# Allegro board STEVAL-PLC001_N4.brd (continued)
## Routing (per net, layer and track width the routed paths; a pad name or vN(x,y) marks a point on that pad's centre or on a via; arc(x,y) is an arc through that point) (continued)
N15516624: length 14.7
  TOP w0.2: v3(35.72,30.91) 36.13,30.91 R71.2 ; TP10.1 46.03,28.37 45.58,27.92 40.71,27.92 39.44,29.2 U13.24 39.44,30.42 38.66,31.2 C54.2
  TOP w0.3: R71.2 37.81,31.78 R72.2 37.84,31.79 C54.2
N15519714: length 19.6
  TOP w0.2: R64.1 45.8,31.78 D27.C 44.9,31.79 R65.1 C50.2 42.96,31.79 42.65,31.48 42.42,31.25 41.39,30.22 U13.21
  TOP w0.3: R64.1 46.48,31.79 51.17,27.1 SW1.2
N15526476: length 2.4
  BOTTOM w0.2: R46.1 77.81,31.55 77.81,31.55 U9.1
N15526659: length 2.4
  BOTTOM w0.2: U7.1 84.06,31.55 84.06,31.55 R32.1
N15526663: length 2.4
  BOTTOM w0.2: U7.2 85.33,31.54 85.31,31.55 R31.1
N15526669: length 2.4
  BOTTOM w0.2: R34.1 86.51,31.55 86.59,31.46 86.59,29.79
N15526673: length 2.4
  BOTTOM w0.2: R36.1 87.81,31.55 87.87,31.5 U7.4
N15644326: length 31.5
  TOP w0.2: v1(37.68,35.36) 37,34.69 R71.1
  POWER PLANE w0.2: v1(37.68,35.36) v1(50.28,47.97)
  LOGIC_PLANE w0.2: v1(54.37,55.8) 53.71,55.14 53.71,50.82 50.86,47.97 v1(50.28,47.97)
  BOTTOM w0.2: R156.2 v1(54.37,55.8)
N15652884: length 20.5
  TOP w0.7: v2(70.65,41.55) 71.69,42.6 71.97,42.6
  TOP w1: 71.97,42.6 72.02,42.65 74.26,42.65 74.31,42.6 L7.2
  BOTTOM w0.4: v2(70.65,41.55) 70.5,41.4 68.51,41.4 68.11,41.8 68.11,43 68.83,43.72 U26.3
  BOTTOM w0.5: C98.1 70.91,42.39 70.91,42.4 ; 70.91,42.4 70.65,42.14 v2(70.65,41.55) ; 70.91,42.4 U26.1
N15653000: length 43
  TOP w0.3: v2(95.45,36.06) 94.88,35.49 75.67,35.49 74.91,36.25 74.91,40.09 74.1,40.9 70.31,40.9 69.93,41.29 69.93,42.77 72.22,45.06 72.22,48.23 71.51,48.94 v2(71.51,50)
  BOTTOM w0.3: 71.67,48.8 71.51,48.95 v2(71.51,50)
  BOTTOM w0.4: v2(95.45,36.06) 96.19,36.8 D48.A
N15853888: length 38.5
  POWER PLANE w0.4: v2(61.71,40.5) 62.66,40.5 68.89,46.73 68.89,46.81 68.93,46.85 68.93,47.02 69.91,47.99 69.91,51.08 69.92,51.09 v2(69.92,51.8)
  BOTTOM w0.4: v2(69.92,51.8) 69.92,56.91 70.85,57.84 R184.2
  BOTTOM w0.6: BT1.1 48.11,40.05 50.56,37.6 59.26,37.6 61.71,40.05 v2(61.71,40.5) BT1.2
N15937224: length 7.2
  TOP w0.2: v1(69.36,81.74) 69.36,82.95 67.67,84.64 v2(66.91,84.64)
  BOTTOM w0.2: U27.104 v1(69.36,81.74)
  BOTTOM w0.3: R163.1 v2(66.91,84.64)
  BOTTOM w0.4: R164.1 R163.1
N15989509: length 58.9
  TOP w0.18: 35.62,32.02 R74.2 35.47,31.87 C53.2 34.73,31.29 34.88,31.14 U13.31
  TOP w0.2: v1(32.02,48.47) 31.98,48.47 28.21,44.7 28.21,35.85 29.63,34.43 35.14,34.43 36.12,33.45 36.12,32.52 35.62,32.02
  POWER PLANE w0.2: v1(32.02,48.47) 34.05,50.51 35.31,50.51 38.18,53.38 57.35,53.38 58.19,54.22 v1(58.19,55.61)
  BOTTOM w0.2: R75.2 57.73,55.67 58.13,55.67 v1(58.19,55.61)
N15989570: length 3.4
  TOP w0.2: R68.2 C55.2 41.21,31.2 40.74,30.73 U13.22
N15989574: length 3.2
  TOP w0.2: R69.2 C57.2 40.31,31.2 40.09,30.98 U13.23
N16126417: length 5.7
  TOP w0.2: v1(45.51,51.4) 45.39,51.52 U15.5
  BOTTOM w0.2: R87.1 42.51,48.8 42.91,49.2 43.31,49.2 v1(45.51,51.4)
N16126447: length 6.5
  TOP w0.18: U15.13 49.38,52.83 49.38,51.9 48.88,51.4 v1(47.91,51.4)
  BOTTOM w0.18: v1(47.91,51.4) 46.92,50.41 46.7,50.41 45.51,49.23 R89.1
N16126488: length 8.3
  TOP w0.18: U15.21 53.39,52.13 53.15,51.89 51.89,51.89 51.57,51.57 51.21,51.57 51.18,51.6 v1(50.31,51.6)
  BOTTOM w0.18: R91.1 49.81,50.96 50.16,50.96 50.31,51.11 v1(50.31,51.6)
N16126496: length 6.2
  TOP w0.18: U15.14 49.89,52.2 49.71,52.02 v1(49.71,51.4)
  BOTTOM w0.18: v1(49.71,51.4) 48.67,51.4 46.51,49.24 R90.2
N16126511: length 5.7
  TOP w0.2: U15.6 45.89,52.18 45.91,52.16 45.91,51.63 v1(46.28,51.26)
  BOTTOM w0.2: v1(46.28,51.26) 46.01,51.26 45.7,50.95 43.76,49.15 43.76,48.91 R88.2
N16423386: length 7.7
  TOP w0.18: v1(50.91,51.16) 52.25,51.16 52.53,51.44 53.36,51.44 53.67,51.75 53.74,51.75 53.89,51.9 U15.22
  BOTTOM w0.18: R92.2 48.75,48.9 48.75,49 v1(50.91,51.16)
N16503177: length 8.7
  TOP w0.3: R81.1 26.71,28.27 D34.C
N16514344: length 78
  TOP w0.8: C86.1 4.32,43 5.61,44.29 ; 5.61,44.11 5.61,44.29 ; 5.61,44.29 Q4.5
  TOP w1: Q4.8 9.47,42.6 8.46,41.6 8.46,32.15 9.46,31.15 14.86,31.15 15.21,30.8 15.21,30.2 14.96,29.95 5.01,29.95 4.71,29.65 4.71,29.2 5.16,28.75 16.16,28.75 16.56,28.35 16.56,27.95 16.16,27.55 6.71,27.55 6.46,27.3 6.46,26.65 6.81,26.3 10.76,26.3 11.11,25.95 11.11,25.4 10.76,25.05 8.31,25.05 8.06,24.8 8.06,24.1 8.31,23.85 11.66,23.85 12.76,22.75 12.76,22.04 12.78,22.02 D39.1
  TOP w1.2: F1.2 12.78,19.66 D39.1
N16514352: length 34
  TOP w0.6: D38.C 7.92,53.97 C90.1 7.97,55.55 R144.1
  TOP w1: Q4.3 Q4.2 Q4.1
  TOP w1.5: C87.1 11.54,47.86 9.74,49.66 Q4.1 9.6,49.8 9.6,52.29 D38.C 9.79,53.99 9.79,60.9 12.63,63.74 L4.1
N16514548: length 12.1
  TOP w0.5: R144.2 7.05,55.55 C90.2
  TOP w0.6: C90.2 7,55.44 4.61,53.05 D38.A
  TOP w0.7: R145.2 3.66,47.35 5.66,49.34 Q4.4 5.66,51.97 D38.A
N16561780: length 5.8
  TOP w0.3: v2(77.28,97.06) 77.28,96.4 76.73,95.85 D11.C
  BOTTOM w0.3: v2(77.28,97.06) 77.28,96.4 76.41,95.53 U6.1
N16578488: length 4.1
  TOP w0.152: v2(71.48,95.8) 71.33,95.8 D10.C
  BOTTOM w0.2: v2(71.48,95.8) 70.32,95.8 69.81,95.3 U3.4
N16596019: length 2.4
  BOTTOM w0.2: U12.2 62.34,22.52 62.36,22.5 R61.1
N16596025: length 2.4
  BOTTOM w0.2: U12.3 61.08,21.95 R60.1
N16605257: length 6.4
  BOTTOM w0.152: R184.1 R185.1
  BOTTOM w0.3: R184.1 70.69,59.08 70.38,59.08 ; 70.38,59.08 70.5,58.95 70.5,58.53 C100.2 ; 70.38,59.08 70.38,59.12 68.86,60.64 U27.6
N16616858: length 1.2
  TOP w0.5: D40.A 7.71,61.21 R142.1
N16634792: length 8.9
  TOP w0.25: D21.A 59.86,23.8 61.67,22 66.63,22 67.11,22.48 R51.1
N16639460: length 2.4
  BOTTOM w0.2: R62.1 63.51,22.5 63.62,22.61 U12.1
N16639519: length 2.4
  BOTTOM w0.2: R59.1 59.81,22.5 59.81,22.5 U12.4
N16642965: length 2.4
  BOTTOM w0.2: 68.39,24.31 68.39,23.3 68.52,23.18 68.52,22.72 68.41,22.62 R57.1
N16642967: length 2.6
  BOTTOM w0.2: R58.1 70.31,23.03 69.67,23.68 U11.1
N16642969: length 2.4
  BOTTOM w0.16: R56.1 67.11,23.06 67.12,23.07 U11.3
N16642971: length 2.6
  BOTTOM w0.2: U11.4 65.86,23.05 65.61,22.81 65.61,22.16 R55.1
N16646826: length 2.7
  BOTTOM w0.2: R53.1 73.46,22.69 74.39,23.63 74.39,24.26
N16646828: length 2.6
  BOTTOM w0.2: R50.1 72.71,22.59 73.12,23 U10.3
N16646830: length 2.9
  BOTTOM w0.2: R54.1 75.41,22.96 75.41,23.37 75.67,23.63 U10.1
N16646832: length 3.2
  BOTTOM w0.2: R49.1 71.95,21.96 72.31,22.32 72.31,23.17 71.86,23.63 U10.4
N16671237: length 2.1
  TOP w0.25: 70.76,11.8 71.88,11.8
  TOP w0.3: 71.88,11.8 72.06,11.8 R29.2 ; 70.76,11.8 70.46,11.8 D15.A
N16671239: length 2.2
  TOP w0.5: R27.2 81.43,12.2 D13.A 80.52,12.21
N16671241: length 1.8
  TOP w0.4: R30.2 65.85,11.66 D16.A
N16671243: length 1.5
  TOP w0.3: D14.A R28.2
N16678102: length 3.7
  TOP w0.2: 64.13,22.5 65.04,22.5 65.3,22.76 65.3,22.93 R52.1
  TOP w0.3: D22.A 63.13,23.07 63.71,22.5 64.13,22.5
N16736638: length 16.7
  TOP w0.3: D41.A v3(93.63,45.35)
  POWER PLANE w0.2: v1(89.01,55.51) 88.56,55.06 88.56,50.03 88.56,50.03 88.56,49.57 88.56,49.57 88.56,46.19 89.26,45.49 93.49,45.49 v3(93.63,45.35)
  BOTTOM w0.2: R143.1 89.3,55.8 v1(89.01,55.51)
N16736836: length 4.2
  TOP w0.2: 91.76,50.59 v1(91.76,50)
  TOP w0.25: U22.2 92.82,51.65 91.76,50.59
  BOTTOM w0.2: U25.5 91.3,49.3 91.76,49.76 v1(91.76,50)
N16736872: length 4.3
  TOP w0.2: 92.38,49.75 92.09,49.46 92.09,49.15 v1(91.74,48.8)
  TOP w0.25: U22.3 92.82,51 92.38,50.56 92.38,49.75
  BOTTOM w0.2: v1(91.74,48.8) 91.71,48.8 U25.6
N16737152: length 7.9
  TOP w0.2: D47.A 94.51,55.6 v2(94.71,55.4)
  BOTTOM w0.25: R149.2 89.7,53.13 90.03,52.8 91.36,52.8 93.96,55.4 v2(94.71,55.4)
N16737156: length 8.5
  LOGIC_PLANE w0.3: v1(92.41,57.51) 92.41,58.06 91.73,58.74 v1(90.62,58.74)
  BOTTOM w0.2: Q5.1 93.06,58.23 93.51,58.68 93.51,59.4 94.51,60.4 94.51,61.2 94.52,61.21 R151.1
  BOTTOM w0.3: Q5.1 92.69,57.88 92.41,57.6 v1(92.41,57.51) ; v1(90.62,58.74) R148.2
N16737176: length 3.5
  TOP w0.4: D47.C v1(96.11,57.35)
  BOTTOM w0.4: v1(96.11,57.35) 96.11,57.95 96.11,58.6 95.51,59.2 Q5.3
N16752352: length 10.5
  TOP w0.4: R37.2 90.03,13.8 J8.1
N16753248: length 12.3
  TOP w0.4: 91.21,14.6 R38.2
  TOP w0.5: 91.21,14.6 92.25,14.6 J9.1
N16769682: length 42.9
  TOP w0.8: 94.55,61.15 D46.4 ; D45.4 93.6,40.6
  TOP w0.99: L7.1 89.4,40.8
  TOP w1: 91.43,40.6 D45.4 ; 91.43,40.6 89.6,40.6 89.4,40.8 ; 91.43,40.6 84.41,47.62 84.41,59.18 86.38,61.15 D46.4
N16781010: length 6.2
  TOP w0.2: v1(50.01,68.6) 50.57,69.16 53.36,69.16 R165.1
  BOTTOM w0.2: v1(50.01,68.6) 50.41,69 U27.48
N16815309: length 4.1
  BOTTOM w0.2: R104.1 79.22,85 79.23,85.01 J18.1
N16815311: length 3.2
  BOTTOM w0.3: J18.2 88.49,85.01 88.5,85 89.25,85 R115.2
N16815356: length 4.1
  BOTTOM w0.2: R105.1 79.21,82.45 79.23,82.47 J18.3
N16815358: length 9.2
  BOTTOM w0.3: R106.2 92.45,81.9 92.15,81.6 89.41,81.6 88.54,82.47 J18.4
N16815404: length 4.1
  BOTTOM w0.2: J18.5 79.23,79.93 79.2,79.9 R108.1
N16815406: length 3.5
  TOP w0.3: R109.2 83.85,79.2 v1(84.71,79.2)
  BOTTOM w0.3: J18.6 85.44,79.93 v1(84.71,79.2)
N16815431: length 28.8
  BOTTOM w0.2: J17.14 24.43,69.72 23.51,68.8 23.51,51.4 24.11,50.8 26.71,50.8 28.11,49.4 R186.2
N16815500: length 20.1
  BOTTOM w0.25: R95.1 R96.1 29.19,71.09 24,71.09 22.71,69.8 22.71,61.17 21.09,59.56 J17.21
N16815530: length 4.2
  BOTTOM w0.25: J18.11 79.23,72.31 78.94,72.6 R113.1
N16815532: length 3.1
  BOTTOM w0.3: R118.2 88.5,72.3 88.49,72.31 J18.12
N16815574: length 4.5
  BOTTOM w0.2: R121.1 77.54,69 78.31,69.77 J18.13
N16815576: length 3.2
  BOTTOM w0.3: J18.14 88.49,69.77 88.52,69.8 R122.2
N16815612: length 3.2
  BOTTOM w0.3: R123.2 88.56,67.25 88.54,67.23 J18.16
N16815702: length 7
  BOTTOM w0.2: J18.19 80.17,62.15 79.51,61.49 79.51,60.65 76.97,58.11 R189.1
N16815735: length 3.1
  BOTTOM w0.25: 87.56,59.61 88.14,60.2 R131.2
  BOTTOM w0.3: 87.56,59.61 J18.22
N16815777: length 3.1
  BOTTOM w0.3: J18.24 88.49,57.07 88.51,57.05 R134.2
N16815800: length 6.8
  BOTTOM w0.3: R187.2 28.3,50.2 26.55,51.94 J17.28
N16815809: length 3.1
  BOTTOM w0.3: J18.26 88.49,54.53 88.51,54.55 R135.2
N16815841: length 3.2
  BOTTOM w0.3: J18.28 88.82,51.99 89.06,51.75 R136.2
N16815880: length 4.3
  BOTTOM w0.3: R138.2 87.16,51 86.59,50.43 J18.30
N16815921: length 34.7
  TOP w0.25: v2(83.71,70) 83.71,69.37 83.3,68.96 v2(83.3,54.26)
  BOTTOM w0.25: v2(83.3,54.26) 83.3,48.11 82.09,46.91 J18.31 ; v2(83.71,70) 83.71,72.8 82.91,73.6 77.52,73.6 R190.1
N16815961: length 25.5
  BOTTOM w0.3: R98.1 39.17,48.6 39.51,48.6 39.91,48.2 39.91,47.11 39.95,47.07 39.95,46.66 39.91,46.62 39.91,46.4 39.31,45.8 37.51,45.8 32.92,41.21 30.26,41.21 30.25,41.2 28.11,41.2 27.51,40.6 23.26,40.6 22.08,41.78 J17.35
N16815963: length 3.9
  BOTTOM w0.2: R188.2 28.63,41.78 J17.36
N16815968: length 3.1
  BOTTOM w0.2: R139.2 88.52,44.4 88.49,44.37 J18.34
N16815983: length 27.8
  BOTTOM w0.3: J17.37 19.16,39.24 17.91,40.49 17.91,42.4 18.51,43 33.31,43 34.51,44.2 34.52,44.2 34.81,44.49 34.81,44.5 36.71,46.4 36.71,47.96 37.41,48.66 R99.1
N16816031: length 2.4
  BOTTOM w0.2: U19.59 45.15,74.7 R101.1
N16816085: length 3.1
  BOTTOM w0.2: U19.56 45.05,76.2 45.31,75.94 45.31,75.09 45.86,74.55 R103.1
N16816140: length 2
  BOTTOM w0.25: U19.54 45.41,77.2 45.56,77.05 R116.1
N16816178: length 2
  BOTTOM w0.25: U19.53 45.41,77.7 45.56,77.85 R111.1
N16816234: length 2
  BOTTOM w0.25: U19.51 45.46,78.7 45.56,78.6 R117.1
N16816260: length 2
  BOTTOM w0.25: U19.50 45.41,79.2 45.56,79.35 R120.1
N16816337: length 2.3
  BOTTOM w0.2: U19.48 44.82,80.2 45.46,80.84 45.94,80.84 R125.1
N16816363: length 2.4
  BOTTOM w0.2: U19.47 44.81,80.7 45.91,81.8 R128.1
N16816449: length 2.4
  BOTTOM w0.25: R133.1 45.95,82.65 45.62,82.32 45.62,82.2 45.34,81.92 45.23,81.92 45,81.7 U19.45
N16816548: length 3.9
  TOP w0.3: R137.2 12.61,85.2 D37.A
N16816568: length 3.9
  TOP w0.3: D36.A 12.61,81.2 R94.2
N16816730: length 21.7
  TOP w0.3: v2(28.06,86.8) 25.84,84.58 16.49,84.58 14.81,86.26 11.84,86.26 11.3,86.8 D37.C
  BOTTOM w0.3: Q3.3 v2(28.06,86.8)
N16816751: length 26.6
  TOP w0.5: D36.C 9.51,82.8 10.11,83.4 v2(10.23,83.4)
  BOTTOM w0.3: Q2.3 33.62,86.2 33.03,86.8 30.49,86.8 29.87,86.18 28.8,86.18 28.42,86.18 13.01,86.18 v2(10.23,83.4)
N16816773: length 24.1
  BOTTOM w0.3: R102.1 36.62,88.61 36.33,88.32 Q2.1 36.7,87.17 37.91,88.38 37.91,89.2 38.91,90.2 49.91,90.2 53.09,87.02 54.05,87.02 R97.2
N16816793: length 3.7
  BOTTOM w0.2: Q3.1 33.47,87.77 R140.2 R141.1
N16817624: length 5.1
  BOTTOM w0.2: R130.1 76.97,64.75 R129.1
  BOTTOM w0.25: J18.17 79.2,64.69 79.12,64.6 77.73,64.6 77.64,64.7 R129.1
N16822475: length 3.9
  TOP w0.2: C4.1 32.68,92.08 31.13,92.08 30.73,92.48 U1.48
  TOP w0.3: R1.1 C4.1
N16822477: length 3.3
  TOP w0.2: U1.47 29.8,91.81 30,91.6 30.7,91.6 31.2,91.1 C3.1 R2.1
N16822479: length 2.3
  TOP w0.2: U1.46 29.3,91.32 C2.1 R3.1
N16822481: length 1.6
  TOP w0.2: U1.44 28.3,91.82 28.26,91.79 28.26,91.52 27.85,91.11 R4.1
N16822499: length 23
  TOP w0.2: U1.41 26.8,91.83 25.22,90.25 23.21,90.25 16.31,97.15 D1.A
N16822523: length 25.2
  TOP w0.2: U1.40 26.3,91.91 24.99,90.61 23.45,90.61 16.81,97.25 16.81,103.9 18.4,105.48 18.9,105.48 18.91,105.5 D2.A
N16822549: length 1.5
  TOP w0.2: U1.42 27.19,92.37 27.19,91.53 26.96,91.3 R5.1
N16822551: length 31
  TOP w0.2: U1.39 25.8,91.9 24.89,91 23.61,91 17.38,97.23 17.38,103.53 18.45,104.6 21.66,104.6 22,104.94 v2(22.43,105.37)
  TOP w0.4: D3.A 26.96,105.45 27.51,106 v2(27.6,106)
  BOTTOM w0.2: v2(27.6,106) 26.54,104.94 22.86,104.94 v2(22.43,105.37)
N16822575: length 30.8
  TOP w0.2: v2(18.03,101.2) 18.03,97.08 23.71,91.4 24.68,91.4 25.3,92.02 U1.38
  TOP w0.4: v2(30.64,105) 30.71,105 31.16,105.45 D4.A
  BOTTOM w0.2: v2(18.03,101.2) 18.03,102.86 18.06,102.89 18.06,102.95 19.42,104.31 29.96,104.31 v2(30.64,105)
N16822613: length 33.8
  TOP w0.2: U1.37 24.8,92.24 24.47,91.92 23.84,91.92 18.72,97.04 v2(18.72,100.6)
  TOP w0.4: v2(36.11,104.4) 36.86,105.15 D5.A
  BOTTOM w0.2: v2(18.72,100.6) 18.72,103.06 19.41,103.75 19.66,103.75 19.86,103.95 35.66,103.95 v2(36.11,104.4)
N16822638: length 36.3
  TOP w0.2: v2(19.36,100) 19.36,96.9 23.15,93.11 U1.36
  TOP w0.4: v2(38.91,105.8) 39.62,105.8 40.02,105.4 D6.A
  BOTTOM w0.2: v2(38.91,105.8) 36.71,103.6 20,103.6 19.36,102.96 v2(19.36,100)
N16822654: length 37.1
  TOP w0.2: v2(20.71,100) 20.26,99.55 20.26,96.55 23.2,93.61 U1.35
  TOP w0.4: v2(45.51,105) 45.91,105.4 D7.A
  BOTTOM w0.2: v2(45.51,105) 38.71,105 34.48,100.77 21.48,100.77 v2(20.71,100)
N16822678: length 42.2
  TOP w0.2: U1.34 23.3,94.11 21.4,96.01 v2(21.4,99)
  TOP w0.4: D8.A 52.71,105.4 v2(53.31,104.8)
  BOTTOM w0.2: v2(53.31,104.8) 51.66,104.8 47.27,100.41 22.8,100.41 21.4,99.01 v2(21.4,99)
N16822815: length 2.5
  TOP w0.2: R6.1 32.46,94.05 31.52,93.11 U1.1
N16822888: length 6.1
  TOP w0.4: R8.2 34.16,94.85 36.01,96.7 36.01,97.56 J2.2
N16822890: length 2.6
  TOP w0.18: U1.2 31.37,93.61 32.47,94.71 32.86,94.71 R8.1
N16822932: length 2.5
  TOP w0.18: U1.4 31.57,94.61 32.61,95.65 R10.1
N16823099: length 11.1
  TOP w0.4: J4.2 40.37,100.5 37.21,100.5 35.23,98.52 35.23,96.97 R10.2
N16823193: length 5.1
  TOP w0.2: 30.3,99.25 31.81,99.25 31.82,99.26 C11.1
  TOP w0.3: C11.1 33.5,99.26 34.68,100.44 R13.2
N16823195: length 5.3
  TOP w0.2: R15.2 R16.1 32.76,100.7 32.06,100 30,100 29.8,99.8 29.8,99.25
N16823486: length 4.4
  BOTTOM w0.2: 43.84,87.46 44.36,86.95 R20.2 ; 43.84,87.46 U2.4 ; 43.84,87.46 43.36,86.98 R18.2
N16823562: length 61.2
  POWER PLANE w0.2: v1(37.85,55.62) 38.91,56.68 55.51,56.68 55.53,56.7 57.41,56.7 58.36,57.65 58.61,57.65 v1(58.96,58.01)
  BOTTOM w0.18: 40.04,87.52 40.31,87.25 40.31,68.62 40.35,68.58 40.35,68.22 40.31,68.18 40.31,58.1 38.26,56.05 ; 37.81,55.6 37.85,55.64
  BOTTOM w0.2: v1(58.96,58.01) 59.25,58.3 59.25,58.48 R21.2 ; v1(37.85,55.62) 37.85,55.64 38.26,56.05
  BOTTOM w0.3: 40.04,87.52 U2.7
  BOTTOM w0.4: 40.04,87.52 39.71,87.2 39.71,86.55 38.71,85.55 TP2.1
N16919862: length 13.3
  BOTTOM w0.2: R162.1 73.96,83.28 71.68,81 69,81 68.8,81.2 68.8,82.82 U27.103 68.86,83.74 R161.1
N16919990: length 8.4
  BOTTOM w0.2: R153.1 53.4,56.6 52.71,56.6 52.51,56.8 52.51,58.86 52.71,59.06 R152.1 54.26,59.31 54.26,59.75 54.35,59.84 54.35,60.68 54.36,60.69 U27.35
N16946294: length 3.6
  BOTTOM w0.2: R159.1 R160.1 68.36,85.04 U27.102
N164994551: length 1.7
  TOP w0.2: U5.14 91.46,99.55 91.11,99.9 R26.2
N164999121: length 9.8
  TOP w0.3: R76.1 23.01,25.64 D29.C
N165089721: length 5.6
  TOP w0.4: v1(43.23,44.6) 42.8,45.02 40.09,45.02 39.73,44.67 Q1.1
  BOTTOM w0.3: R84.2 43.75,44.6 v1(43.23,44.6)
N170697731: length 6.5
  BOTTOM w0.2: R191.2 92.87,67.55 92.87,68.8
  BOTTOM w0.3: 92.87,68.8 92.87,69.51 93.29,69.93 J23.7
N1681503127: length 2.8
  BOTTOM w0.25: R100.2 31.01,74.3 31.41,74.7 U19.28
N1681503130: length 2.7
  BOTTOM w0.25: R114.2 31.51,76 31.71,76.2 U19.31
N1681503132: length 2.8
  BOTTOM w0.25: R107.2 31.31,76.8 31.71,77.2 U19.33
N1681503133: length 2.7
  BOTTOM w0.25: R110.2 32.07,77.6 32.17,77.7 U19.34
N1681503135: length 2.9
  BOTTOM w0.25: U19.36 31.63,78.7 31.32,79.01 31.32,79.01 31.04,79.3 R112.2
N1681503136: length 3
  BOTTOM w0.25: U19.37 31.86,79.2 31.01,80.05 R119.2
N1681503138: length 2.9
  BOTTOM w0.25: U19.39 31.71,80.2 31.01,80.9 R124.2
N1681503139: length 3.1
  BOTTOM w0.25: U19.40 32.17,80.7 31.12,81.75 R127.2
N1681503141: length 3
  BOTTOM w0.25: U19.42 32.17,81.7 31.27,82.6 R132.2

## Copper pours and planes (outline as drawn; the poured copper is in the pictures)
24V_FIELD on TOP: 17.46,23.4 41.11,23.4 41.11,19.8 40.96,19.65 32.76,19.65 32.34,19.23 32.34,19.1 32.36,15.25 31.96,14.85 16.76,14.85 16.76,22.65
24V_FIELD on BOTTOM: 17.51,23.4 41.11,23.4 41.11,19.8 40.91,19.6 32.71,19.6 32.31,19.2 32.31,15.2 31.91,14.8 16.71,14.8 16.71,22.6
24V_FIELD on LOGIC_PLANE: 7.71,117.6 91.51,117.6 97.51,111.4 97.51,92.8 96.11,91 14.91,91 14.79,69.55 14.91,41 33.51,25.6 94.74,26 97.44,24.45 97.51,7.8 91.11,1.8 16.91,1.8 16.51,2.2 16.51,20.5 16.31,21 1.71,34.4 1.71,110.8
GND_CLT1 on POWER PLANE: 27.28,92.89 31.16,92.89 32.15,93.88 32.15,99.92 35.38,103.15 43.13,103.15 48.22,98.06 48.22,90.26 47.9,89.94 27.57,89.94 27.08,90.43 27.08,92.69
GND_EARTH on TOP, BOTTOM: 4.91,6.2 4.91,11.2 1.11,11.2 1.11,6.2
GND_EARTH on BOTTOM: 1.11,27.3 4.71,27.3 4.71,11.5 1.71,11.5 1.11,12.1
GND_EARTH on BOTTOM: 2.18,10.03 3.8,10.03 3.8,8.4 2.18,8.4
GND_FIELD on TOP: 23.12,98.85 24.95,98.85 25.36,98.44 30.76,98.44 31.11,98.75 31.61,98.75 31.81,98.65 31.81,95.2 31.51,94.9 30.84,94.9 30.84,93.16 25.56,93.16 25.61,94.5 23.81,94.5 23.12,95.19
GND_FIELD on BOTTOM: 25.26,98.49 30.54,98.49 30.54,93.21 25.26,93.21
GND_FIELD on POWER PLANE: 5.86,115.3 7.86,117.5 9.26,117.5 91.66,117.65 97.66,111.45 97.61,92.75 96.46,90.95 48.37,91.01 48.37,98.16 43.14,103.4 35.36,103.38 31.95,99.93 31.95,93.93 31,92.98 27.24,92.98 26.98,92.72 26.98,91.04 15.31,91.05 15.06,69.3 15.21,40.95 33.26,25.75 54.35,25.75 57.18,23.48 57.18,16.43 57.79,16.04 72.62,15.97 72.6,16.77 72.6,19.79 73.79,21.11 89.26,21.19 89.21,25.97 95.51,26.05 97.46,24.22 97.56,7.6 91.36,1.75 38.31,1.45 38.25,1.4 16.76,1.4 16.8,1.44 16.8,20.52 1.76,34.2 2.17,110.3 2.18,110.31 2.16,111.1
GND_LCD on LOGIC_PLANE: 29.06,35.2 37.46,35.2 40.06,37.8 40.06,40 39.26,40.8 39.26,42.4 38.86,42.8 35.71,45.8 28.91,45.8 28.86,35.4
GND_LOGIC on LOGIC_PLANE: 15.91,89.8 96.31,89.6 97.31,88.6 97.25,29.16 95.51,27.2 33.11,27.4 15.91,41.8
GND_SIGNAL on POWER PLANE: 88.8,25.2 88.8,23.54 88.82,21.44 73.17,21.41 72.12,19.95 72.16,19.93 72.16,18.44 72.14,16.38 57.95,16.39 57.39,16.66 57.39,24.05 59.43,26.09 88.77,26.09
Net_3 on POWER PLANE: 22.24,107.68 27.57,107.68 27.73,107.52 27.73,106.77 27.07,106.11 22.53,106.11 22.07,106.57 22.07,107.51
N16514344 on TOP (solid shape): 9.86,44.23 5.26,44.23 5.26,48.13 9.86,48.13

Small or netless copper shapes (teardrops, artwork), in the pictures only: 72 on TOP, 91 on BOTTOM, 14 on POWER PLANE, 7 on LOGIC_PLANE

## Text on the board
Ref Des/Assembly Bottom: 18 | STM32F746ZGTx | STMPS2151STR
Ref Des/Silkscreen Bottom: FIELD SUPPLY | .0 to.7 High-Side 8x Digital Out | Q1.0 to Q1.3 Low-Side 4X Digital Out | Input for demo mode | 37 | 29 | 9 | 5 | 38 | 14 | 18 | 1 | MORPHO CONNECTOR FOR EXPANSION | 24V | Input | +
Ref Des/Assembly Top: STLD40DPUR | EMIF08-LCD04M16
Ref Des/Silkscreen Top: Surge Test Capacitor | 8xDigital IN | High-Side | GND | FIELD SUPPLY | FIELD | 24V | /MISO | MISO | Connect I1.XH to 24V when I1.XL active | Connect I1.XL to GND when I1.XH active | OUTPUT | High/Low-Side | 4xDigital IN | non-isolated input | K | SPI Settings | 0H | 0L | 1H | 1L | 2H | 2L | 3H | 3L | 8bits | 16bits | STL42P6LLF6 | 0 to 7 -> | <- .0 to.3 | 5V | EARTH | USART | MCU PROG | . | I0 | CLT01-38SQ7 | + | Q0 | 0 | 1 | 2 | 3 | 4 | 5 | ISO8200AQ | 6 | 7 | CLT03-2Q3 | .3 | IPS4260L | Q1 | I1 | FOR EVALUATION ONLY | NOT FCC APPROVED FOR RESALE | STEVAL-PLC001V1 | -
XSECTION_CHART: STACKUP TABLE | Unit = Mils | # | 1 | 2 | 3 | 4 | NAME | TOP | POWER PLANE | LOGIC_PLANE | BOTTOM | TYPE | SURFACE | CONDUCTOR | DIELECTRIC | PLANE | MATERIAL | AIR | COPPER | FR-4 | TOTAL THICKNESS | THICKNESS | 0 | 1.200787 | 8 | 28.799213 | TOLERANCE | +0/-0
DIMENSION: FIGURE | FINISHED_SIZE | 5.905512 | 12.98819 | 28.34646 | 33.46063 | 39.37008 | 41.72835 | 51.1811 | 55.11811 | 137.7953 | DRILL CHART: TOP to BOTTOM | ALL UNITS ARE IN MILS | PLATED | NON-PLATED | QTY | 414 | 393 | 10 | 4 | 12 | 32 | 24 | 9
PLACE_BOUND_TOP: FIGURE | FINISHED_SIZE | 12.98819 | DRILL CHART: TOP to POWER PLANE | ALL UNITS ARE IN MILS | PLATED | QTY | 18
DISPLAY_BOTTOM: FIGURE | FINISHED_SIZE | 33.46063x25.59055 | 59.05906x31.5 | SLOT HOLES: TOP to BOTTOM | ALL UNITS ARE IN MILS | PLATED | QTY | 2
